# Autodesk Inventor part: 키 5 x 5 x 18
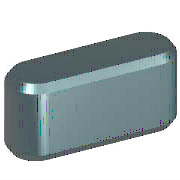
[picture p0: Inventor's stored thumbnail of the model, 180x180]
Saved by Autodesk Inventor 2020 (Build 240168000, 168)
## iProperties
Created: 2012-02
Part Number: 키 5 x 5 x 18
Material: 강철, 연강
Description: 키 및 해당 키홈
Document SubType Name: Modeling
Standard: KS B 1311
Designer: mduedu
Standards Organization: KS
Language: ko-KR
Size Designation: 5 x 5 x 18
Categories: <MemberInstance><Categories><Category DisplayName="샤프트 부품" InternalName="7f7aeb1f-a693-4053-b835-cee3144e0d98" Mnemonic="SHFT"><Category DisplayName="키" Interna
Density: 7.86 g/cm^3
Mass: 3.27476 g
Surface Area: 3.57848 cm^2
Volume: 0.416636 cm^3
Appearance: 노란색
IsCustomPart: 1
Author: mduedu
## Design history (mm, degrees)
workplane "Work Plane1"
workplane "Work Plane2"
sketch "스케치1"
  geometry: L1 (2.5, 2.5)-(15.5, 2.5); L2 (15.5, -2.5)-(2.5, -2.5); L3 (0, 9.4)-(0, -7.4) reference; L4 (-5, 0)-(30, 0) reference; L5 (18, 0)-(18, 7); A1 r 2.5 centre (2.5, 0) between (2.5, 2.5) and (2.5, -2.5); A2 r 2.5 centre (15.5, 0) between (15.5, -2.5) and (15.5, 2.5)
  constraints: 6 end point, 5 point on circle, 4 tangent, 3 point on line, 2 centre point, 1 horizontal, 1 parallel, 1 perpendicular
  dimensions: "d0" = 2.5 radius of A1 (= 0.5 x PB); "d13" = 2.5 radius of A2 (= 0.5 x PB); "d14" = 18 distance between parallel lines of L5 L3 (= NLG)
extrude "본체1" new body sketch "스케치1" taper "d3" = 0 deg; stored distance "d4" = 10
workplane "Work Plane3"
body "Solid1"
chamfer "모따기1" distance "d8" = 0.4 (= PHH); stored, may be unused: second distance "d9" = 0.4 (= PHH), angle "d15" = 45 deg
other parameters: "d1" = -3 (= -PNT), "d2" = 2 (= PH - PNT), "NLG" = 18 [user parameter; used in 3 equation terms], "PB" = 5 [user parameter; used in 2 equation terms], "PNT" = 3 [user parameter; used in 2 equation terms], "PH" = 5 [user parameter; used in 1 equation term], "PHH" = 0.4 [user parameter; used in 2 equation terms], "d10" = 0, "d16" = 0, "d17" = 0, "d18" = 0, "WDMIN" = 12 [user parameter], "PLB2" = 18 (= NLG) [user parameter], "WDMAX" = 17 [user parameter], "PLB1" = 18 (= NLG) [user parameter], "RR" = 0.16 [user parameter], "PUEB" = 2.3 [user parameter]
